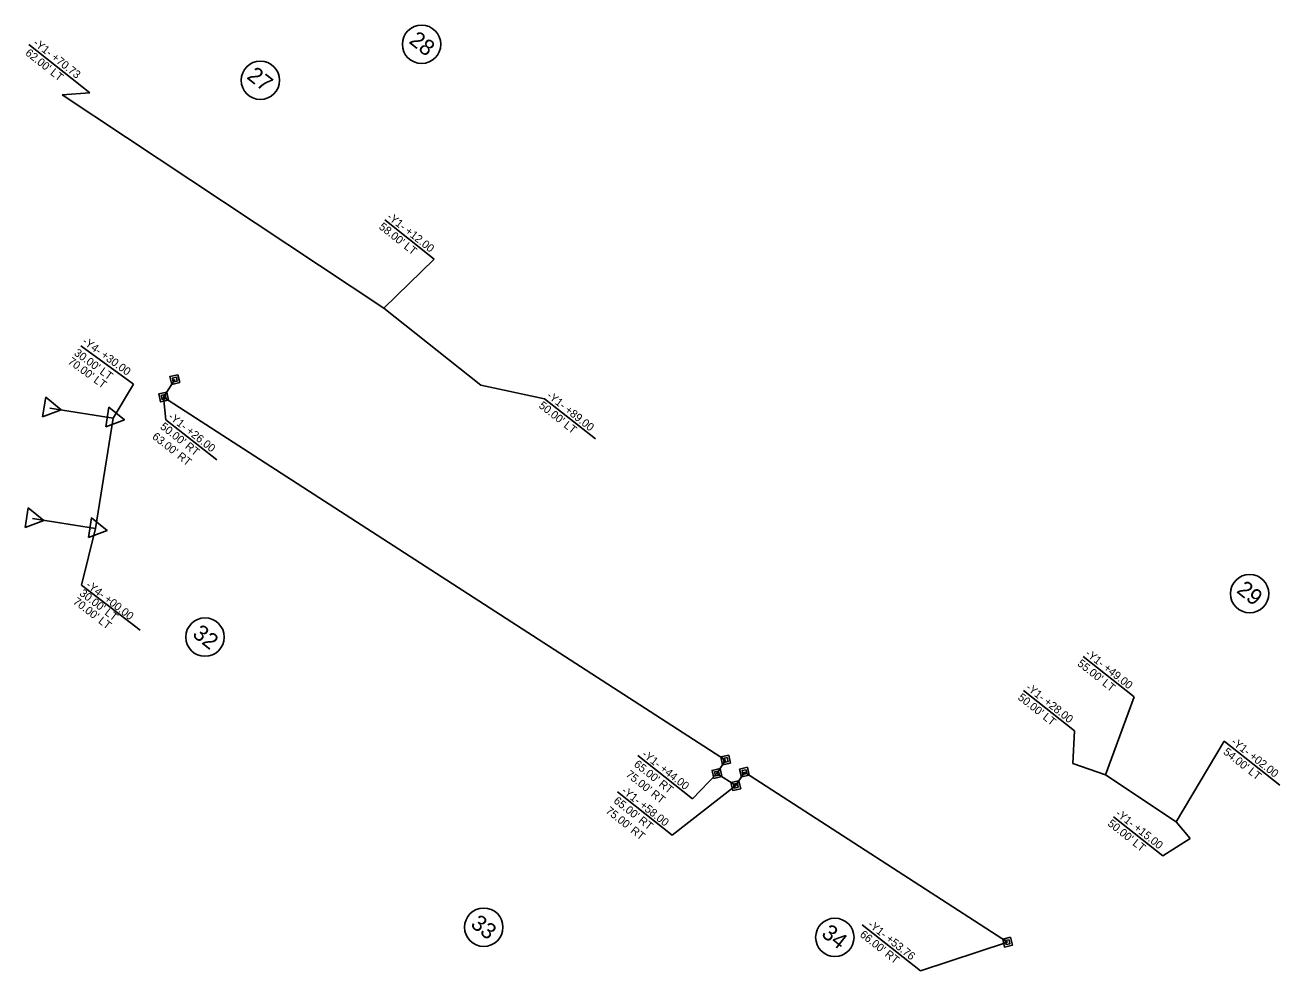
# Model space of a CAD drawing. Extents: x 1779796 to 1783527, y 810952 to 815815.
# Drawn here: x 1782743 to 1783527, y 813733 to 814324 of the extents above; entities that cross this region are included whole.
import ezdxf

# ---------------------------------------------------------------- set-up
doc = ezdxf.new("R2010")
doc.units = 0
for name, color, linetype in [('Prop Easement Construction', 7, 'Continuous'), ('Prop Easement Construction Station Offsets', 7, 'Continuous'), ('Prop Easement Permanent Utility', 7, 'Continuous'), ('Prop Easement Permanent Utility Station Offsets', 7, 'Continuous'), ('Prop Parcel Number CELL', 7, 'Continuous'), ('Prop Parcel Number Text', 7, 'Continuous'), ('Prop ROW Marker CELL', 7, 'Continuous'), ('Prop ROW Permanent Easement CELL', 7, 'Continuous'), ('Prop ROW RW CA Lines', 7, 'Continuous'), ('Prop ROW Station Offsets', 7, 'Continuous')]:
    doc.layers.add(name, color=color, linetype=linetype)

msp = doc.modelspace()

# ---------------------------------------------------------------- linework, layer by layer
at = {"layer": 'Prop Easement Construction'}
for p, q in [((1782766.46, 814280.93), (1782967.57, 814147.59)), ((1782967.57, 814147.59), (1783028.13, 814099.37)), ((1783397.98, 813862.87), (1783418.37, 813855.77)), ((1783418.37, 813855.77), (1783462.48, 813826.38)), ((1783462.48, 813826.38), (1783471.28, 813816))]:
    msp.add_line(p, q, dxfattribs=at)
at = {"layer": 'Prop Easement Construction Station Offsets'}
for p, q in [((1782783.84, 814282.15), (1782745.71, 814312.34)), ((1782998.89, 814178.28), (1782968.04, 814202.71)), ((1783099.68, 814065.81), (1783067.9, 814090.97)), ((1783436.19, 813904.57), (1783404.4, 813929.74)), ((1783399.01, 813883.32), (1783367.23, 813908.49)), ((1783527.35, 813849.32), (1783492.56, 813876.87)), ((1783454.17, 813805.29), (1783423.32, 813829.71))]:
    msp.add_line(p, q, dxfattribs=at)
for points in [[(1782783.84, 814282.15), (1782766.46, 814280.93)], [(1782998.89, 814178.28), (1782967.57, 814147.59)], [(1783067.9, 814090.97), (1783028.13, 814099.37)], [(1783436.19, 813904.57), (1783418.37, 813855.77)], [(1783399.01, 813883.32), (1783397.98, 813862.87)], [(1783492.56, 813876.87), (1783462.48, 813826.38)], [(1783454.17, 813805.29), (1783471.28, 813816)]]:
    msp.add_lwpolyline(points, dxfattribs=at)
at = {"layer": 'Prop Easement Permanent Utility'}
for p, q in [((1782836.93, 814102.93), (1782829.93, 814091.97)), ((1782829.93, 814091.97), (1783181.01, 813865.11)), ((1783181.01, 813865.11), (1783175.63, 813856.68)), ((1783192.81, 813857.57), (1783187.42, 813849.14)), ((1783192.81, 813857.57), (1783357.19, 813751.27)), ((1783175.63, 813856.68), (1783187.42, 813849.14))]:
    msp.add_line(p, q, dxfattribs=at)
at = {"layer": 'Prop Easement Permanent Utility Station Offsets'}
for p, q in [((1782829.93, 814091.97), (1782831.35, 814077.82)), ((1782863.13, 814052.66), (1782831.35, 814077.82)), ((1783160.28, 813840.86), (1783126.09, 813867.93)), ((1783175.63, 813856.68), (1783160.28, 813840.86)), ((1783147.6, 813818.07), (1783113.41, 813845.14)), ((1783187.42, 813849.14), (1783147.6, 813818.07)), ((1783302.77, 813733.3), (1783266.44, 813762.07))]:
    msp.add_line(p, q, dxfattribs=at)
msp.add_lwpolyline([(1783302.77, 813733.3), (1783357.19, 813751.27)], dxfattribs=at)
at = {"layer": 'Prop Parcel Number CELL'}
for p, q in [((1782991.08, 814312.49), (1782991.08, 814312.49)), ((1782890.37, 814289.98), (1782890.37, 814289.98)), ((1783508.43, 813969.12), (1783508.43, 813969.12)), ((1782855.76, 813941.93), (1782855.76, 813941.93)), ((1783029.95, 813760.6), (1783029.95, 813760.6)), ((1783249.27, 813754.25), (1783249.27, 813754.25))]:
    msp.add_line(p, q, dxfattribs=at)
for centre in [(1782991.08, 814312.49), (1782890.37, 814289.98), (1783508.43, 813969.12), (1782855.76, 813941.93), (1783029.95, 813760.6), (1783249.27, 813754.25)]:
    msp.add_circle(centre, 12, dxfattribs=at)
at = {"layer": 'Prop ROW Marker CELL'}
for p, q in [((1782836.93, 814102.93), (1782836.93, 814102.93)), ((1782758.82, 814085.13), (1782758.82, 814085.13)), ((1782829.93, 814091.97), (1782829.93, 814091.97)), ((1782798.34, 814078.89), (1782798.34, 814078.89)), ((1782747.91, 814015.98), (1782747.91, 814015.98)), ((1782787.43, 814009.75), (1782787.43, 814009.75)), ((1783181.01, 813865.11), (1783181.01, 813865.11)), ((1783192.81, 813857.57), (1783192.81, 813857.57)), ((1783175.63, 813856.68), (1783175.63, 813856.68)), ((1783187.42, 813849.14), (1783187.42, 813849.14)), ((1783357.19, 813751.27), (1783357.19, 813751.27))]:
    msp.add_line(p, q, dxfattribs=at)
for points in [[(1782754.28, 814079.53), (1782756.25, 814091.85), (1782765.95, 814084)], [(1782793.79, 814073.29), (1782795.76, 814085.61), (1782805.46, 814077.77)], [(1782743.37, 814010.38), (1782745.34, 814022.7), (1782755.04, 814014.86)], [(1782782.88, 814004.15), (1782784.85, 814016.47), (1782794.55, 814008.62)]]:
    msp.add_lwpolyline(points, close=True, dxfattribs=at)
at = {"layer": 'Prop ROW Permanent Easement CELL'}
for points in [[(1782838.87, 814105.96), (1782839.97, 814100.99), (1782834.99, 814099.89), (1782833.9, 814104.87)], [(1782837.9, 814104.44), (1782838.45, 814101.96), (1782835.96, 814101.41), (1782835.42, 814103.9)], [(1782831.87, 814095.01), (1782832.96, 814090.03), (1782827.99, 814088.94), (1782826.9, 814093.91)], [(1782830.9, 814093.49), (1782831.45, 814091), (1782828.96, 814090.46), (1782828.41, 814092.94)], [(1783182.95, 813868.14), (1783184.05, 813863.17), (1783179.07, 813862.08), (1783177.98, 813867.05)], [(1783181.98, 813866.62), (1783182.53, 813864.14), (1783180.04, 813863.59), (1783179.5, 813866.08)], [(1783177.57, 813859.72), (1783178.66, 813854.74), (1783173.69, 813853.65), (1783172.59, 813858.62)], [(1783176.6, 813858.2), (1783177.14, 813855.71), (1783174.66, 813855.17), (1783174.11, 813857.65)], [(1783194.75, 813860.6), (1783195.84, 813855.63), (1783190.87, 813854.53), (1783189.78, 813859.5)], [(1783193.78, 813859.08), (1783194.32, 813856.6), (1783191.84, 813856.05), (1783191.29, 813858.53)], [(1783189.36, 813852.17), (1783190.45, 813847.2), (1783185.48, 813846.11), (1783184.39, 813851.08)], [(1783188.39, 813850.66), (1783188.94, 813848.17), (1783186.45, 813847.62), (1783185.9, 813850.11)], [(1783359.13, 813754.3), (1783360.23, 813749.33), (1783355.26, 813748.23), (1783354.16, 813753.2)], [(1783358.16, 813752.78), (1783358.71, 813750.3), (1783356.22, 813749.75), (1783355.68, 813752.23)]]:
    msp.add_lwpolyline(points, close=True, dxfattribs=at)
at = {"layer": 'Prop ROW RW CA Lines'}
for p, q in [((1782758.82, 814085.13), (1782798.34, 814078.89)), ((1782798.34, 814078.89), (1782787.43, 814009.75)), ((1782747.91, 814015.98), (1782787.43, 814009.75))]:
    msp.add_line(p, q, dxfattribs=at)
at = {"layer": 'Prop ROW Station Offsets'}
for p, q in [((1782811.19, 814100), (1782778.16, 814124.07)), ((1782798.34, 814078.89), (1782811.19, 814100)), ((1782787.43, 814009.75), (1782778.64, 813974.47)), ((1782778.64, 813974.47), (1782815.24, 813946.34))]:
    msp.add_line(p, q, dxfattribs=at)

# ---------------------------------------------------------------- texts
at = {"layer": 'Prop Easement Construction Station Offsets'}
for s, p in [('-Y1- +70.73', (1782748.05, 814312.53)), ("62.00' LT", (1782743.09, 814306.26)), ('-Y1- +12.00', (1782968.99, 814203.87)), ("58.00' LT", (1782964.02, 814197.6)), ('-Y1- +89.00', (1783068.84, 814092.13)), ("50.00' LT", (1783063.88, 814085.86)), ("55.00' LT", (1783400.38, 813924.63)), ('-Y1- +49.00', (1783405.35, 813930.9)), ("50.00' LT", (1783363.21, 813903.38)), ('-Y1- +28.00', (1783368.18, 813909.65)), ('-Y1- +02.00', (1783496.51, 813875.65)), ("54.00' LT", (1783491.54, 813869.38)), ("50.00' LT", (1783419.3, 813824.61)), ('-Y1- +15.00', (1783424.27, 813830.88))]:
    msp.add_text(s, height=5, rotation=321.63093, dxfattribs=at).set_placement(p)
at = {"layer": 'Prop Easement Permanent Utility Station Offsets'}
for s, p in [('-Y1- +26.00', (1782832.3, 814078.98)), ("63.00' RT", (1782822.36, 814066.44)), ("50.00' RT", (1782827.33, 814072.71)), ('-Y1- +44.00', (1783128.28, 813867.89)), ("75.00' RT", (1783118.35, 813855.34)), ("65.00' RT", (1783123.31, 813861.61)), ("65.00' RT", (1783110.63, 813838.83)), ('-Y1- +58.00', (1783115.6, 813845.1)), ("75.00' RT", (1783105.67, 813832.56)), ('-Y1- +53.76', (1783269.45, 813761.5)), ("66.00' RT", (1783264.49, 813755.22))]:
    msp.add_text(s, height=5, rotation=321.63093, dxfattribs=at).set_placement(p)
at = {"layer": 'Prop Parcel Number Text'}
for s, p in [('28', (1782982.63, 814313.69)), ('27', (1782881.33, 814291.46)), ('29', (1783499.7, 813970.24)), ('32', (1782847.33, 813942.81)), ('33', (1783021.11, 813761.48)), ('34', (1783240.29, 813755.48))]:
    msp.add_text(s, height=10, rotation=321.63093, dxfattribs=at).set_placement(p)
at = {"layer": 'Prop ROW Station Offsets'}
for s, rotation, p in [('-Y4- +30.00', 323.91886, (1782778.68, 814125.83)), ("70.00' LT", 323.91886, (1782769.66, 814113.29)), ("30.00' LT", 323.91886, (1782773.52, 814118.59)), ('-Y4- +00.00', 322.44735, (1782780.93, 813973.7)), ("30.00' LT", 322.44735, (1782776.93, 813968.5)), ("70.00' LT", 322.44735, (1782772.94, 813963.3))]:
    msp.add_text(s, height=5, rotation=rotation, dxfattribs=at).set_placement(p)

doc.saveas('drawing.dxf')
